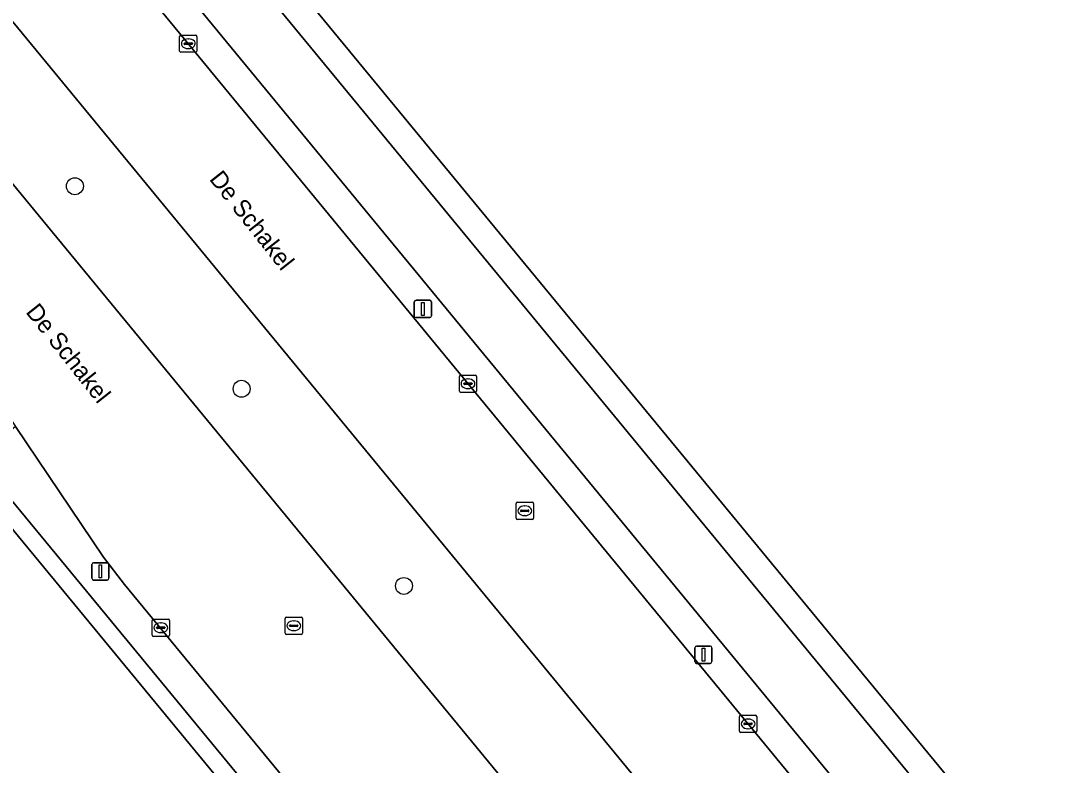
# Model space of a CAD drawing. Extents: x 156141 to 158132, y 385651 to 388333.
# Drawn here: x 157265.8 to 157326.3, y 386292.4 to 386335.6 of the extents above; entities that cross this region are included whole.
import ezdxf

# ---------------------------------------------------------------- set-up
doc = ezdxf.new("R2010")
doc.units = 0
for name, color, linetype in [('IMGEO_Berm_groen', 7, 'Continuous'), ('IMGEO_Boom', 7, 'Continuous'), ('IMGEO_Erf', 7, 'Continuous'), ('IMGEO_Fietspad_gesloten', 7, 'Continuous'), ('IMGEO_Groenvoorziening', 7, 'Continuous'), ('IMGEO_Hek', 7, 'Continuous'), ('IMGEO_Kolk', 7, 'Continuous'), ('IMGEO_Lichtmast', 7, 'Continuous'), ('IMGEO_Openbare_ruimte_label', 7, 'Continuous'), ('IMGEO_Rijbaan_lokaal_gesloten', 7, 'Continuous'), ('IMGEO_Rioolput', 7, 'Continuous'), ('IMGEO_Voetpad_open', 7, 'Continuous')]:
    doc.layers.add(name, color=color, linetype=linetype)

msp = doc.modelspace()

# ---------------------------------------------------------------- linework, layer by layer
at = {"layer": 'IMGEO_Berm_groen'}
for points in [[(157213.61, 386417.964), (157209.596, 386414.647), (157210.786, 386412.789), (157212.168, 386411.116), (157320.799, 386279.156), (157324.262, 386275.047), (157332.608, 386264.801), (157349.183, 386247.253)], [(157205.755, 386407.826), (157203.781, 386410.196), (157199.193, 386406.39), (157201.153, 386404.033), (157327.942, 386250), (157336.115, 386240.102), (157337.285, 386238.671)], [(157342.288, 386241.546), (157341.401, 386242.711), (157335.682, 386250), (157205.755, 386407.826)], [(157326.865, 386274.627), (157230.994, 386391.037)]]:
    msp.add_lwpolyline(points, dxfattribs=at)
at = {"layer": 'IMGEO_Boom'}
for centre in [(157268.887, 386325.993), (157278.547, 386314.257), (157287.953, 386302.83)]:
    msp.add_circle(centre, 0.489, dxfattribs=at)
at = {"layer": 'IMGEO_Erf'}
for points in [[(157234.228, 386395.166), (157332.344, 386276.123), (157332.523, 386276.279), (157333.62, 386275.073), (157335.421, 386273.192), (157337.278, 386271.367), (157339.859, 386268.963), (157352.266, 386257.409), (157352.344, 386257.32), (157382.139, 386277.036), (157430.229, 386313.885)], [(157213.671, 386179.31), (157318.008, 386237.675), (157310.24, 386250.894), (157308.881, 386253.009), (157305.737, 386257.034), (157297.068, 386267.539), (157250.016, 386324.597), (157249.125, 386323.863), (157233.385, 386310.904), (157232.673, 386310.318), (157226.757, 386305.447), (157227.019, 386305.124), (157227.309, 386305.361), (157228.122, 386304.37), (157229.365, 386302.857), (157226.965, 386300.89), (157224.909, 386303.4), (157225.394, 386303.796), (157225.13, 386304.108), (157163.286, 386253.19), (157161.441, 386255.415), (157161.905, 386255.778), (157223.541, 386305.983)]]:
    msp.add_lwpolyline(points, dxfattribs=at)
at = {"layer": 'IMGEO_Fietspad_gesloten'}
for points in [[(157331.128, 386275.064), (157233.279, 386393.841)], [(157230.994, 386391.037), (157326.865, 386274.627)]]:
    msp.add_lwpolyline(points, dxfattribs=at)
at = {"layer": 'IMGEO_Groenvoorziening'}
msp.add_lwpolyline([(157250.614, 386325.491), (157248.932, 386324.105), (157249.125, 386323.863), (157250.016, 386324.597), (157297.068, 386267.539), (157305.737, 386257.034), (157308.881, 386253.009), (157310.24, 386250.894), (157318.008, 386237.675), (157319.091, 386238.264), (157310.849, 386252.423)], close=True, dxfattribs=at)
at = {"layer": 'IMGEO_Hek'}
msp.add_lwpolyline([(157297.068, 386267.539), (157250.016, 386324.597), (157233.385, 386310.904)], dxfattribs=at)
at = {"layer": 'IMGEO_Kolk'}
for p, q in [((157274.957, 386333.828), (157274.957, 386334.68)), ((157275.032, 386334.754), (157275.884, 386334.754)), ((157275.445, 386334.534), (157275.47, 386334.534)), ((157275.958, 386334.68), (157275.958, 386333.828)), ((157275.216, 386334.248), (157275.216, 386334.26)), ((157275.654, 386334.211), (157275.256, 386334.211)), ((157275.259, 386334.297), (157275.657, 386334.297)), ((157275.468, 386333.974), (157275.443, 386333.974)), ((157275.7, 386334.26), (157275.7, 386334.248)), ((157275.884, 386333.754), (157275.032, 386333.754)), ((157291.164, 386314.122), (157291.164, 386314.974)), ((157291.239, 386315.048), (157292.091, 386315.048)), ((157291.423, 386314.542), (157291.423, 386314.554)), ((157291.466, 386314.591), (157291.864, 386314.591)), ((157291.652, 386314.828), (157291.677, 386314.828)), ((157291.907, 386314.554), (157291.907, 386314.542)), ((157292.165, 386314.974), (157292.165, 386314.122)), ((157292.091, 386314.048), (157291.239, 386314.048)), ((157291.861, 386314.505), (157291.463, 386314.505)), ((157291.675, 386314.268), (157291.65, 386314.268)), ((157273.365, 386299.983), (157273.365, 386300.835)), ((157273.44, 386300.909), (157274.292, 386300.909)), ((157273.853, 386300.689), (157273.878, 386300.689)), ((157274.366, 386300.835), (157274.366, 386299.983)), ((157273.624, 386300.403), (157273.624, 386300.415)), ((157274.062, 386300.366), (157273.664, 386300.366)), ((157273.667, 386300.452), (157274.065, 386300.452)), ((157273.876, 386300.129), (157273.851, 386300.129)), ((157274.108, 386300.415), (157274.108, 386300.403)), ((157274.292, 386299.909), (157273.44, 386299.909)), ((157307.392, 386294.413), (157307.392, 386295.265)), ((157307.467, 386295.339), (157308.319, 386295.339)), ((157308.393, 386295.265), (157308.393, 386294.413)), ((157307.651, 386294.833), (157307.651, 386294.845)), ((157308.089, 386294.796), (157307.691, 386294.796)), ((157307.694, 386294.882), (157308.092, 386294.882)), ((157307.903, 386294.559), (157307.878, 386294.559)), ((157307.88, 386295.119), (157307.905, 386295.119)), ((157308.135, 386294.845), (157308.135, 386294.833)), ((157308.319, 386294.339), (157307.467, 386294.339))]:
    msp.add_line(p, q, dxfattribs=at)
for points in [[(157274.957, 386333.828), (157274.957, 386334.68)], [(157275.032, 386334.754), (157275.884, 386334.754)], [(157275.958, 386334.68), (157275.958, 386333.828)], [(157275.884, 386333.754), (157275.032, 386333.754)], [(157291.164, 386314.122), (157291.164, 386314.974)], [(157291.239, 386315.048), (157292.091, 386315.048)], [(157292.165, 386314.974), (157292.165, 386314.122)], [(157292.091, 386314.048), (157291.239, 386314.048)], [(157273.365, 386299.983), (157273.365, 386300.835)], [(157273.44, 386300.909), (157274.292, 386300.909)], [(157274.366, 386300.835), (157274.366, 386299.983)], [(157274.292, 386299.909), (157273.44, 386299.909)], [(157307.392, 386294.413), (157307.392, 386295.265)], [(157307.467, 386295.339), (157308.319, 386295.339)], [(157308.393, 386295.265), (157308.393, 386294.413)], [(157308.319, 386294.339), (157307.467, 386294.339)]]:
    msp.add_lwpolyline(points, dxfattribs=at)
for centre, radius, start, end in [((157275.034, 386334.678), 0.0765, 91.55205, 178.44795), ((157275.034, 386334.678), 0.0765, 91.55205, 178.44795), ((157275.882, 386334.678), 0.0765, 1.55205, 88.44795), ((157275.882, 386334.678), 0.0765, 1.55205, 88.44795), ((157275.256, 386334.257), 0.0403, 85.87752, 175.75265), ((157275.253, 386334.247), 0.0366, 178.93798, 274.71019), ((157275.657, 386334.254), 0.043, 264.86636, 352.45326), ((157275.661, 386334.259), 0.0386, 1.73085, 96.63898), ((157275.034, 386333.83), 0.0765, 181.55205, 268.44795), ((157275.034, 386333.83), 0.0765, 181.55205, 268.44795), ((157275.882, 386333.83), 0.0765, 271.55205, 358.44795), ((157275.882, 386333.83), 0.0765, 271.55205, 358.44795), ((157291.241, 386314.972), 0.0765, 91.55205, 178.44795), ((157291.241, 386314.972), 0.0765, 91.55205, 178.44795), ((157291.463, 386314.551), 0.0403, 85.87752, 175.75265), ((157291.46, 386314.541), 0.0366, 178.93798, 274.71019), ((157291.864, 386314.548), 0.043, 264.86636, 352.45326), ((157291.868, 386314.553), 0.0386, 1.73085, 96.63898), ((157292.089, 386314.972), 0.0765, 1.55205, 88.44795), ((157292.089, 386314.972), 0.0765, 1.55205, 88.44795), ((157291.241, 386314.124), 0.0765, 181.55205, 268.44795), ((157291.241, 386314.124), 0.0765, 181.55205, 268.44795), ((157292.089, 386314.124), 0.0765, 271.55205, 358.44795), ((157292.089, 386314.124), 0.0765, 271.55205, 358.44795), ((157273.442, 386300.833), 0.0765, 91.55205, 178.44795), ((157273.442, 386300.833), 0.0765, 91.55205, 178.44795), ((157274.29, 386300.833), 0.0765, 1.55205, 88.44795), ((157274.29, 386300.833), 0.0765, 1.55205, 88.44795), ((157273.442, 386299.985), 0.0765, 181.55205, 268.44795), ((157273.442, 386299.985), 0.0765, 181.55205, 268.44795), ((157273.664, 386300.412), 0.0403, 85.87752, 175.75265), ((157273.661, 386300.402), 0.0366, 178.93798, 274.71019), ((157274.065, 386300.409), 0.043, 264.86636, 352.45326), ((157274.069, 386300.414), 0.0386, 1.73085, 96.63898), ((157274.29, 386299.985), 0.0765, 271.55205, 358.44795), ((157274.29, 386299.985), 0.0765, 271.55205, 358.44795), ((157307.469, 386295.263), 0.0765, 91.55205, 178.44795), ((157307.469, 386295.263), 0.0765, 91.55205, 178.44795), ((157308.317, 386295.263), 0.0765, 1.55205, 88.44795), ((157308.317, 386295.263), 0.0765, 1.55205, 88.44795), ((157307.691, 386294.842), 0.0403, 85.87752, 175.75265), ((157307.688, 386294.832), 0.0366, 178.93798, 274.71019), ((157308.092, 386294.839), 0.043, 264.86636, 352.45326), ((157308.096, 386294.844), 0.0386, 1.73085, 96.63898), ((157307.469, 386294.415), 0.0765, 181.55205, 268.44795), ((157307.469, 386294.415), 0.0765, 181.55205, 268.44795), ((157308.317, 386294.415), 0.0765, 271.55205, 358.44795), ((157308.317, 386294.415), 0.0765, 271.55205, 358.44795)]:
    msp.add_arc(centre, radius, start, end, dxfattribs=at)
for centre, major_axis, ratio, start_param, end_param in [((157275.444, 386334.254), (-0.387, 0.002), 0.722429, 4.712389, 7.853982), ((157275.469, 386334.254), (-0.39, 0.002), 0.717154, 1.570796, 4.712389), ((157291.651, 386314.548), (-0.387, 0.002), 0.722429, 4.712389, 7.853982), ((157291.676, 386314.548), (-0.39, 0.002), 0.717154, 1.570796, 4.712389), ((157273.852, 386300.409), (-0.387, 0.002), 0.722429, 4.712389, 7.853982), ((157273.877, 386300.409), (-0.39, 0.002), 0.717154, 1.570796, 4.712389), ((157307.879, 386294.839), (-0.387, 0.002), 0.722429, 4.712389, 7.853982), ((157307.904, 386294.839), (-0.39, 0.002), 0.717154, 1.570796, 4.712389)]:
    msp.add_ellipse(centre, major_axis=major_axis, ratio=ratio, start_param=start_param, end_param=end_param, dxfattribs=at)
at = {"layer": 'IMGEO_Lichtmast'}
for p, q in [((157288.654, 386319.385), (157289.444, 386319.385)), ((157289.444, 386319.385), (157288.654, 386319.385)), ((157288.554, 386318.485), (157288.554, 386319.285)), ((157288.554, 386319.285), (157288.554, 386318.485)), ((157289.544, 386319.285), (157289.544, 386318.485)), ((157289.544, 386318.485), (157289.544, 386319.285)), ((157289.444, 386318.385), (157288.654, 386318.385)), ((157288.654, 386318.385), (157289.444, 386318.385)), ((157269.868, 386303.273), (157269.868, 386304.073)), ((157269.868, 386304.073), (157269.868, 386303.273)), ((157269.968, 386304.173), (157270.758, 386304.173)), ((157270.758, 386304.173), (157269.968, 386304.173)), ((157270.858, 386304.073), (157270.858, 386303.273)), ((157270.858, 386303.273), (157270.858, 386304.073)), ((157270.758, 386303.173), (157269.968, 386303.173)), ((157269.968, 386303.173), (157270.758, 386303.173)), ((157304.812, 386298.444), (157304.812, 386299.244)), ((157304.812, 386299.244), (157304.812, 386298.444)), ((157304.912, 386299.344), (157305.702, 386299.344)), ((157305.702, 386299.344), (157304.912, 386299.344)), ((157305.802, 386299.244), (157305.802, 386298.444)), ((157305.802, 386298.444), (157305.802, 386299.244)), ((157305.702, 386298.344), (157304.912, 386298.344)), ((157304.912, 386298.344), (157305.702, 386298.344))]:
    msp.add_line(p, q, dxfattribs=at)
for points in [[(157288.974, 386319.26), (157289.124, 386319.26), (157289.124, 386318.51), (157288.974, 386318.51), (157288.974, 386319.26)], [(157270.288, 386304.048), (157270.438, 386304.048), (157270.438, 386303.298), (157270.288, 386303.298), (157270.288, 386304.048)], [(157305.232, 386299.219), (157305.382, 386299.219), (157305.382, 386298.469), (157305.232, 386298.469), (157305.232, 386299.219)]]:
    msp.add_lwpolyline(points, dxfattribs=at)
for centre, start, end in [((157288.654, 386319.285), 90, 180), ((157288.654, 386319.285), 90, 180), ((157289.444, 386319.285), 0, 90), ((157289.444, 386319.285), 360, 90), ((157288.654, 386318.485), 180, 270), ((157288.654, 386318.485), 180, 270), ((157289.444, 386318.485), 270, 0), ((157289.444, 386318.485), 270, 0), ((157269.968, 386304.073), 90, 180), ((157269.968, 386304.073), 90, 180), ((157270.758, 386304.073), 0, 90), ((157270.758, 386304.073), 360, 90), ((157269.968, 386303.273), 180, 270), ((157269.968, 386303.273), 180, 270), ((157270.758, 386303.273), 270, 0), ((157270.758, 386303.273), 270, 0), ((157304.912, 386299.244), 90, 180), ((157304.912, 386299.244), 90, 180), ((157305.702, 386299.244), 0, 90), ((157305.702, 386299.244), 360, 90), ((157304.912, 386298.444), 180, 270), ((157304.912, 386298.444), 180, 270), ((157305.702, 386298.444), 270, 0), ((157305.702, 386298.444), 270, 0)]:
    msp.add_arc(centre, 0.1, start, end, dxfattribs=at)
at = {"layer": 'IMGEO_Rijbaan_lokaal_gesloten'}
for points in [[(157200.977, 386413.621), (157203.099, 386411.016), (157203.781, 386410.196), (157205.755, 386407.826), (157335.682, 386250), (157341.401, 386242.711), (157342.288, 386241.546), (157344.37, 386238.82), (157346.391, 386236.066), (157355.377, 386240.641), (157355.147, 386240.882), (157352.86, 386243.28), (157351.407, 386244.818), (157349.349, 386247.071), (157349.183, 386247.253), (157332.608, 386264.801), (157324.262, 386275.047), (157320.799, 386279.156), (157212.168, 386411.116), (157210.786, 386412.789), (157209.596, 386414.647), (157209.078, 386415.949)], [(157327.507, 386224.107), (157341.674, 386233.351), (157339.581, 386235.895), (157339.51, 386235.998), (157337.285, 386238.671), (157336.115, 386240.102), (157327.942, 386250), (157201.153, 386404.033)], [(157192.877, 386402.642), (157194.1, 386401.515), (157255.15, 386327.344), (157257.428, 386324.032), (157265.451, 386312.065), (157270.545, 386304.503), (157271.759, 386302.908), (157316.481, 386248.624), (157325.045, 386238.218)]]:
    msp.add_lwpolyline(points, dxfattribs=at)
at = {"layer": 'IMGEO_Rioolput'}
for p, q in [((157294.453, 386306.759), (157294.453, 386307.611)), ((157294.528, 386307.685), (157295.38, 386307.685)), ((157294.941, 386307.465), (157294.966, 386307.465)), ((157295.454, 386307.611), (157295.454, 386306.759)), ((157295.38, 386306.685), (157294.528, 386306.685)), ((157294.712, 386307.179), (157294.712, 386307.191)), ((157295.15, 386307.142), (157294.752, 386307.142)), ((157294.755, 386307.228), (157295.153, 386307.228)), ((157294.964, 386306.905), (157294.939, 386306.905)), ((157295.196, 386307.191), (157295.196, 386307.179)), ((157281.07, 386300.098), (157281.07, 386300.95)), ((157281.145, 386301.024), (157281.997, 386301.024)), ((157281.558, 386300.804), (157281.583, 386300.804)), ((157282.071, 386300.95), (157282.071, 386300.098)), ((157281.997, 386300.024), (157281.145, 386300.024)), ((157281.329, 386300.518), (157281.329, 386300.53)), ((157281.767, 386300.481), (157281.369, 386300.481)), ((157281.372, 386300.567), (157281.77, 386300.567)), ((157281.581, 386300.244), (157281.556, 386300.244)), ((157281.813, 386300.53), (157281.813, 386300.518))]:
    msp.add_line(p, q, dxfattribs=at)
for points in [[(157294.453, 386306.759), (157294.453, 386307.611)], [(157294.528, 386307.685), (157295.38, 386307.685)], [(157295.454, 386307.611), (157295.454, 386306.759)], [(157295.38, 386306.685), (157294.528, 386306.685)], [(157281.07, 386300.098), (157281.07, 386300.95)], [(157281.145, 386301.024), (157281.997, 386301.024)], [(157282.071, 386300.95), (157282.071, 386300.098)], [(157281.997, 386300.024), (157281.145, 386300.024)]]:
    msp.add_lwpolyline(points, dxfattribs=at)
for centre, radius, start, end in [((157294.53, 386307.609), 0.0765, 91.55205, 178.44795), ((157294.53, 386307.609), 0.0765, 91.55205, 178.44795), ((157295.378, 386307.609), 0.0765, 1.55205, 88.44795), ((157295.378, 386307.609), 0.0765, 1.55205, 88.44795), ((157294.53, 386306.761), 0.0765, 181.55205, 268.44795), ((157294.53, 386306.761), 0.0765, 181.55205, 268.44795), ((157294.752, 386307.188), 0.0403, 85.87752, 175.75265), ((157294.749, 386307.178), 0.0366, 178.93798, 274.71019), ((157295.153, 386307.185), 0.043, 264.86636, 352.45326), ((157295.157, 386307.19), 0.0386, 1.73085, 96.63898), ((157295.378, 386306.761), 0.0765, 271.55205, 358.44795), ((157295.378, 386306.761), 0.0765, 271.55205, 358.44795), ((157281.147, 386300.948), 0.0765, 91.55205, 178.44795), ((157281.147, 386300.948), 0.0765, 91.55205, 178.44795), ((157281.995, 386300.948), 0.0765, 1.55205, 88.44795), ((157281.995, 386300.948), 0.0765, 1.55205, 88.44795), ((157281.147, 386300.1), 0.0765, 181.55205, 268.44795), ((157281.147, 386300.1), 0.0765, 181.55205, 268.44795), ((157281.369, 386300.527), 0.0403, 85.87752, 175.75265), ((157281.366, 386300.517), 0.0366, 178.93798, 274.71019), ((157281.77, 386300.524), 0.043, 264.86636, 352.45326), ((157281.774, 386300.529), 0.0386, 1.73085, 96.63898), ((157281.995, 386300.1), 0.0765, 271.55205, 358.44795), ((157281.995, 386300.1), 0.0765, 271.55205, 358.44795)]:
    msp.add_arc(centre, radius, start, end, dxfattribs=at)
for centre, major_axis, ratio, start_param, end_param in [((157294.94, 386307.185), (-0.387, 0.002), 0.722429, 4.712389, 7.853982), ((157294.965, 386307.185), (-0.39, 0.002), 0.717154, 1.570796, 4.712389), ((157281.557, 386300.524), (-0.387, 0.002), 0.722429, 4.712389, 7.853982), ((157281.582, 386300.524), (-0.39, 0.002), 0.717154, 1.570796, 4.712389)]:
    msp.add_ellipse(centre, major_axis=major_axis, ratio=ratio, start_param=start_param, end_param=end_param, dxfattribs=at)
at = {"layer": 'IMGEO_Voetpad_open'}
for points in [[(157233.279, 386393.841), (157331.128, 386275.064), (157332.344, 386276.123), (157234.228, 386395.166)], [(157325.045, 386238.218), (157322.521, 386236.083), (157315.535, 386247.907), (157316.481, 386248.624), (157271.759, 386302.908), (157270.545, 386304.503), (157265.451, 386312.065), (157264.546, 386311.336), (157211.154, 386376.22)], [(157209.826, 386374.969), (157249.344, 386327.032), (157250.614, 386325.491), (157310.849, 386252.423), (157319.091, 386238.264), (157322.186, 386232.946), (157323.219, 386231.171)]]:
    msp.add_lwpolyline(points, dxfattribs=at)

# ---------------------------------------------------------------- texts
at = {"layer": 'IMGEO_Openbare_ruimte_label'}
for p in [(157276.637, 386326.397), (157265.998, 386318.695)]:
    msp.add_text('De Schakel', height=1, rotation=308.30199, dxfattribs=at).set_placement(p)

doc.saveas('drawing.dxf')
